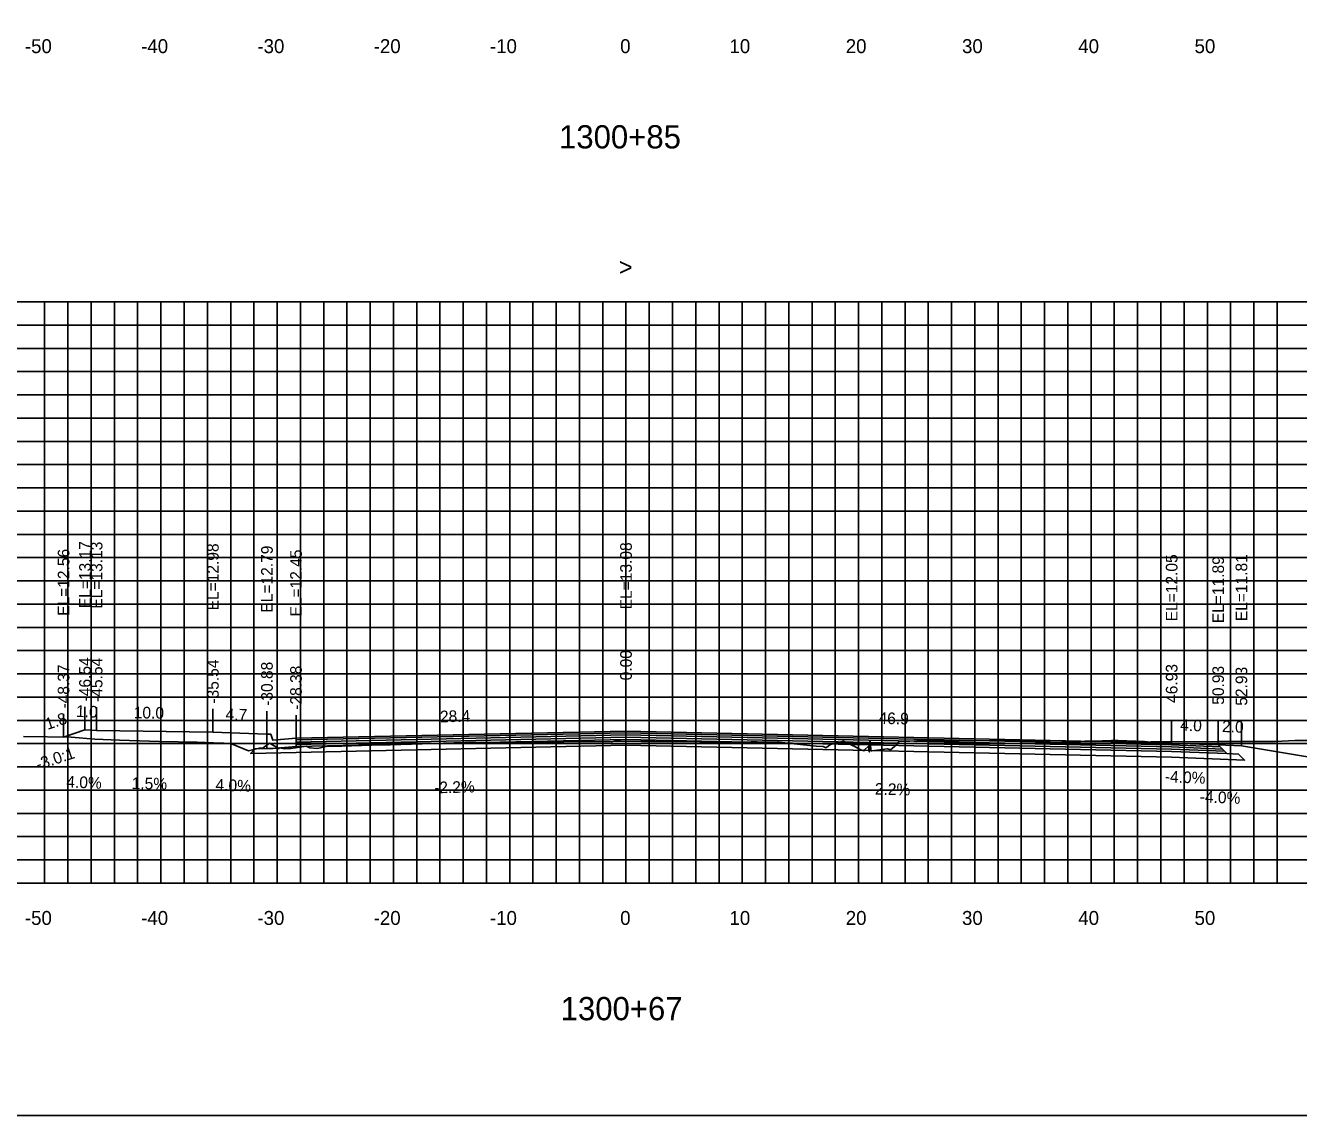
# Model space of a CAD drawing. Extents: x 1797714 to 1804825, y 249015 to 250269.
# Drawn here: x 1802239.4 to 1802348.8, y 250079.4 to 250173.2 of the extents above; entities that cross this region are included whole.
import ezdxf

# ---------------------------------------------------------------- set-up
doc = ezdxf.new("R2010")
doc.units = 0
for name, color, linetype in [('1', 7, 'Continuous'), ('10', 7, 'Continuous'), ('3', 7, 'Continuous'), ('4', 7, 'Continuous'), ('60', 7, 'Continuous'), ('BASE', 7, 'Continuous'), ('CL-CNST', 7, 'Continuous'), ('Level 62', 7, 'Continuous'), ('LOWER BINDER', 7, 'Continuous'), ('M-ROADS', 7, 'Continuous'), ('UPPER BINDER', 7, 'Continuous'), ('WEARING', 7, 'Continuous')]:
    doc.layers.add(name, color=color, linetype=linetype)

msp = doc.modelspace()

# ---------------------------------------------------------------- linework, layer by layer
for p, q in [((1802242.63, 250111.99), (1802242.63, 250113.99)), ((1802244.47, 250112.6), (1802244.47, 250114.6)), ((1802245.47, 250112.56), (1802245.47, 250114.56)), ((1802255.47, 250112.41), (1802255.47, 250114.41)), ((1802260.12, 250112.23), (1802260.12, 250114.23)), ((1802291, 250112.51), (1802291, 250114.51)), ((1802262.62, 250111.89), (1802262.62, 250113.89)), ((1802337.93, 250111.48), (1802337.93, 250113.48)), ((1802341.93, 250111.32), (1802341.93, 250113.32)), ((1802343.93, 250111.24), (1802343.93, 250113.24))]:
    msp.add_line(p, q)
for points in [[(1802141, 250079.43), (1802441, 250079.43), (1802441, 250269.43), (1802141, 250269.43)], [(1802262.62, 250111.89), (1802260.62, 250111.73), (1802260.45, 250112.23), (1802260.12, 250112.23), (1802260.12, 250111.01), (1802260.62, 250111.01), (1802262.62, 250111.17)], [(1802262.62, 250111.89), (1802260.62, 250111.73), (1802260.45, 250112.23), (1802260.12, 250112.23), (1802260.12, 250111.01), (1802260.62, 250111.01), (1802262.62, 250111.17)]]:
    msp.add_lwpolyline(points, close=True)
at = {"layer": '60'}
for p, q in [((1802141, 250099.43), (1802441, 250099.43)), ((1802241, 250099.37), (1802241, 250099.43)), ((1802251, 250099.37), (1802251, 250099.43)), ((1802261, 250099.37), (1802261, 250099.43)), ((1802271, 250099.37), (1802271, 250099.43)), ((1802281, 250099.37), (1802281, 250099.43)), ((1802291, 250099.37), (1802291, 250099.43)), ((1802301, 250099.37), (1802301, 250099.43)), ((1802311, 250099.37), (1802311, 250099.43)), ((1802321, 250099.37), (1802321, 250099.43)), ((1802331, 250099.37), (1802331, 250099.43)), ((1802341, 250099.37), (1802341, 250099.43))]:
    msp.add_line(p, q, dxfattribs=at)
at = {"layer": 'BASE'}
msp.add_lwpolyline([(1802337.93, 250110.26), (1802344.2, 250110.01), (1802343.68, 250110.53), (1802342.68, 250110.57), (1802337.93, 250110.76), (1802291, 250111.79), (1802262.62, 250111.17), (1802260.62, 250111.01), (1802260.12, 250111.01), (1802259.12, 250110.98), (1802258.71, 250110.58), (1802262.62, 250110.67), (1802291, 250111.29)], close=True, dxfattribs=at)
at = {"layer": 'CL-CNST'}
msp.add_lwpolyline([(1802242.63, 250111.99), (1802244.47, 250112.6), (1802245.47, 250112.56), (1802255.47, 250112.41), (1802260.12, 250112.23), (1802260.45, 250112.23), (1802260.62, 250111.73), (1802262.62, 250111.89), (1802291, 250112.51), (1802337.93, 250111.48), (1802341.93, 250111.32), (1802343.93, 250111.24), (1802364.93, 250107.74), (1802368.93, 250107.74), (1802382.11, 250111.03)], dxfattribs=at)
at = {"layer": 'Level 62'}
for p, q in [((1802141, 250149.43), (1802441, 250149.43)), ((1802241, 250099.43), (1802241, 250149.43)), ((1802243, 250099.43), (1802243, 250149.43)), ((1802245, 250099.43), (1802245, 250149.43)), ((1802247, 250099.43), (1802247, 250149.43)), ((1802249, 250099.43), (1802249, 250149.43)), ((1802251, 250099.43), (1802251, 250149.43)), ((1802253, 250099.43), (1802253, 250149.43)), ((1802255, 250099.43), (1802255, 250149.43)), ((1802257, 250099.43), (1802257, 250149.43)), ((1802259, 250099.43), (1802259, 250149.43)), ((1802261, 250099.43), (1802261, 250149.43)), ((1802263, 250099.43), (1802263, 250149.43)), ((1802265, 250099.43), (1802265, 250149.43)), ((1802267, 250099.43), (1802267, 250149.43)), ((1802269, 250099.43), (1802269, 250149.43)), ((1802271, 250099.43), (1802271, 250149.43)), ((1802273, 250099.43), (1802273, 250149.43)), ((1802275, 250099.43), (1802275, 250149.43)), ((1802277, 250099.43), (1802277, 250149.43)), ((1802279, 250099.43), (1802279, 250149.43)), ((1802281, 250099.43), (1802281, 250149.43)), ((1802283, 250099.43), (1802283, 250149.43)), ((1802285, 250099.43), (1802285, 250149.43)), ((1802287, 250099.43), (1802287, 250149.43)), ((1802289, 250099.43), (1802289, 250149.43)), ((1802291, 250099.43), (1802291, 250149.43)), ((1802293, 250099.43), (1802293, 250149.43)), ((1802295, 250099.43), (1802295, 250149.43)), ((1802297, 250099.43), (1802297, 250149.43)), ((1802299, 250099.43), (1802299, 250149.43)), ((1802301, 250099.43), (1802301, 250149.43)), ((1802303, 250099.43), (1802303, 250149.43)), ((1802305, 250099.43), (1802305, 250149.43)), ((1802307, 250099.43), (1802307, 250149.43)), ((1802309, 250099.43), (1802309, 250149.43)), ((1802311, 250099.43), (1802311, 250149.43)), ((1802313, 250099.43), (1802313, 250149.43)), ((1802315, 250099.43), (1802315, 250149.43)), ((1802317, 250099.43), (1802317, 250149.43)), ((1802319, 250099.43), (1802319, 250149.43)), ((1802321, 250099.43), (1802321, 250149.43)), ((1802323, 250099.43), (1802323, 250149.43)), ((1802325, 250099.43), (1802325, 250149.43)), ((1802327, 250099.43), (1802327, 250149.43)), ((1802329, 250099.43), (1802329, 250149.43)), ((1802331, 250099.43), (1802331, 250149.43)), ((1802333, 250099.43), (1802333, 250149.43)), ((1802335, 250099.43), (1802335, 250149.43)), ((1802337, 250099.43), (1802337, 250149.43)), ((1802339, 250099.43), (1802339, 250149.43)), ((1802341, 250099.43), (1802341, 250149.43)), ((1802343, 250099.43), (1802343, 250149.43)), ((1802345, 250099.43), (1802345, 250149.43)), ((1802347, 250099.43), (1802347, 250149.43)), ((1802141, 250147.43), (1802441, 250147.43)), ((1802141, 250145.43), (1802441, 250145.43)), ((1802141, 250143.43), (1802441, 250143.43)), ((1802141, 250141.43), (1802441, 250141.43)), ((1802141, 250139.43), (1802441, 250139.43)), ((1802141, 250137.43), (1802441, 250137.43)), ((1802141, 250135.43), (1802441, 250135.43)), ((1802141, 250133.43), (1802441, 250133.43)), ((1802141, 250131.43), (1802441, 250131.43)), ((1802141, 250129.43), (1802441, 250129.43)), ((1802141, 250127.43), (1802441, 250127.43)), ((1802141, 250125.43), (1802441, 250125.43)), ((1802141, 250123.43), (1802441, 250123.43)), ((1802141, 250121.43), (1802441, 250121.43)), ((1802141, 250119.43), (1802441, 250119.43)), ((1802141, 250117.43), (1802441, 250117.43)), ((1802141, 250115.43), (1802441, 250115.43)), ((1802141, 250113.43), (1802441, 250113.43)), ((1802141, 250111.43), (1802441, 250111.43)), ((1802141, 250109.43), (1802441, 250109.43)), ((1802141, 250107.43), (1802441, 250107.43)), ((1802141, 250105.43), (1802441, 250105.43)), ((1802141, 250103.43), (1802441, 250103.43)), ((1802141, 250101.43), (1802441, 250101.43)), ((1802141, 250099.43), (1802441, 250099.43))]:
    msp.add_line(p, q, dxfattribs=at)
at = {"layer": 'LOWER BINDER'}
for points in [[(1802262.62, 250111.55), (1802291, 250112.17), (1802337.93, 250111.14), (1802342.29, 250110.96), (1802342.48, 250110.77), (1802337.93, 250110.95), (1802291, 250111.98), (1802262.62, 250111.36)], [(1802262.62, 250111.36), (1802291, 250111.98), (1802337.93, 250110.95), (1802342.48, 250110.77), (1802342.68, 250110.57), (1802337.93, 250110.76), (1802291, 250111.79), (1802262.62, 250111.17)]]:
    msp.add_lwpolyline(points, close=True, dxfattribs=at)
at = {"layer": 'M-ROADS'}
msp.add_lwpolyline([(1802239.17, 250112.03), (1802243.28, 250111.98), (1802245.33, 250111.8), (1802247.45, 250111.73), (1802250.88, 250111.6), (1802254.11, 250111.56), (1802255.51, 250111.51), (1802256.23, 250111.46), (1802256.29, 250111.46), (1802256.42, 250111.46), (1802257.06, 250111.41), (1802258.52, 250110.82), (1802259.46, 250111.05), (1802259.8, 250111.07), (1802260.33, 250111.46), (1802261, 250111.09), (1802261.15, 250110.99), (1802261.15, 250111.03), (1802261.18, 250111.07), (1802261.65, 250110.98), (1802262, 250111.02), (1802262.21, 250111.02), (1802263.48, 250111.2), (1802263.82, 250111.07), (1802264.46, 250111.02), (1802265.21, 250111.17), (1802265.49, 250111.22), (1802265.53, 250111.22), (1802265.69, 250111.19), (1802269.11, 250111.29), (1802270.71, 250111.33), (1802277.15, 250111.53), (1802277.31, 250111.53), (1802279.56, 250111.52), (1802279.87, 250111.53), (1802280.06, 250111.53), (1802282.13, 250111.52), (1802283.42, 250111.54), (1802283.53, 250111.54), (1802283.97, 250111.55), (1802287.37, 250111.6), (1802288.04, 250111.6), (1802289.73, 250111.59), (1802290.01, 250111.63), (1802290.09, 250111.64), (1802290.55, 250111.63), (1802292.34, 250111.6), (1802293.51, 250111.62), (1802297.36, 250111.58), (1802299.13, 250111.57), (1802299.77, 250111.55), (1802300.74, 250111.58), (1802301.5, 250111.54), (1802301.78, 250111.57), (1802301.85, 250111.58), (1802302.27, 250111.58), (1802304.11, 250111.56), (1802307.37, 250111.22), (1802307.95, 250111.17), (1802308.18, 250111.08), (1802308.59, 250111.36), (1802309.71, 250111.65), (1802310.54, 250111.24), (1802310.68, 250111.17), (1802310.72, 250111.16), (1802311.13, 250110.92), (1802311.17, 250110.89), (1802311.18, 250110.89), (1802311.18, 250110.89), (1802311.19, 250110.89), (1802311.49, 250110.82), (1802311.52, 250110.88), (1802311.87, 250111.2), (1802311.92, 250110.72), (1802311.93, 250111.35), (1802311.94, 250111.47), (1802312, 250111.64), (1802312.06, 250110.91), (1802312.08, 250110.81), (1802312.08, 250110.8), (1802312.14, 250110.8), (1802313.49, 250110.97), (1802313.76, 250110.88), (1802314.27, 250111.33), (1802314.49, 250111.65), (1802315.42, 250111.65), (1802315.86, 250111.66), (1802315.89, 250111.64), (1802315.91, 250111.65), (1802315.92, 250111.67), (1802315.93, 250111.67), (1802315.95, 250111.61), (1802316.08, 250111.67), (1802316.58, 250111.66), (1802319.08, 250111.66), (1802328.3, 250111.7), (1802328.86, 250111.62), (1802330.45, 250111.64), (1802331.99, 250111.68), (1802332.77, 250111.7), (1802333.34, 250111.7), (1802335.59, 250111.62), (1802336.13, 250111.56), (1802336.14, 250111.57), (1802336.23, 250111.57), (1802336.61, 250111.57), (1802341.89, 250111.62), (1802346.86, 250111.61), (1802348.53, 250111.71), (1802350.02, 250111.71)], dxfattribs=at)
at = {"layer": 'UPPER BINDER'}
msp.add_lwpolyline([(1802262.62, 250111.55), (1802291, 250112.17), (1802337.93, 250111.14), (1802342.29, 250110.96), (1802342.09, 250111.16), (1802337.93, 250111.33), (1802291, 250112.36), (1802262.62, 250111.74)], close=True, dxfattribs=at)
at = {"layer": 'WEARING'}
msp.add_lwpolyline([(1802337.93, 250111.33), (1802342.09, 250111.16), (1802341.93, 250111.32), (1802337.93, 250111.48), (1802291, 250112.51), (1802262.62, 250111.89), (1802262.62, 250111.74), (1802291, 250112.36)], close=True, dxfattribs=at)

# ---------------------------------------------------------------- texts
msp.add_text('-3.0:1', height=1, rotation=18.4349).set_placement((1802240.43, 250109.13))
at = {"layer": '1'}
for s, p in [('1300+85', (1802285.24, 250162.63)), ('1300+67', (1802285.38, 250087.63))]:
    msp.add_text(s, height=2, dxfattribs=at).set_placement(p)
at = {"layer": '10'}
for s, p in [('-50', (1802239.3, 250170.83)), ('-40', (1802249.3, 250170.83)), ('-30', (1802259.3, 250170.83)), ('-20', (1802269.3, 250170.83)), ('-10', (1802279.3, 250170.83)), ('0', (1802290.5, 250170.83)), ('10', (1802299.9, 250170.83)), ('20', (1802309.9, 250170.83)), ('30', (1802319.9, 250170.83)), ('40', (1802329.9, 250170.83)), ('50', (1802339.9, 250170.83)), ('-50', (1802239.3, 250095.83)), ('-40', (1802249.3, 250095.83)), ('-30', (1802259.3, 250095.83)), ('-20', (1802269.3, 250095.83)), ('-10', (1802279.3, 250095.83)), ('0', (1802290.5, 250095.83)), ('10', (1802299.9, 250095.83)), ('20', (1802309.9, 250095.83)), ('30', (1802319.9, 250095.83)), ('40', (1802329.9, 250095.83)), ('50', (1802339.9, 250095.83))]:
    msp.add_text(s, height=1.2, dxfattribs=at).set_placement(p)
at = {"layer": '3'}
for s, p in [('EL=13.17', (1802244.97, 250123.08)), ('EL=13.13', (1802245.97, 250123.04)), ('EL=12.98', (1802255.97, 250122.89)), ('EL=12.79', (1802260.62, 250122.7)), ('EL=13.08', (1802291.5, 250122.98)), ('EL=12.56', (1802243.13, 250122.42)), ('EL=12.45', (1802263.12, 250122.36)), ('EL=12.05', (1802338.43, 250121.95)), ('EL=11.89', (1802342.43, 250121.79)), ('EL=11.81', (1802344.43, 250121.96)), ('0.00', (1802291.5, 250116.87)), ('-46.54', (1802244.97, 250115.06)), ('-45.54', (1802245.97, 250115.02)), ('-35.54', (1802255.97, 250114.87)), ('-30.88', (1802260.62, 250114.68)), ('-48.37', (1802243.13, 250114.45)), ('-28.38', (1802263.12, 250114.34)), ('46.93', (1802338.43, 250114.93)), ('50.93', (1802342.43, 250114.77)), ('52.93', (1802344.43, 250114.69))]:
    msp.add_text(s, height=1, rotation=90, dxfattribs=at).set_placement(p)
at = {"layer": '4'}
for s, rotation, p in [('1.8', 18.4349, (1802241.25, 250112.6)), ('1.0', 357.7094, (1802243.69, 250113.73)), ('10.0', 359.1406, (1802248.66, 250113.61)), ('4.7', 357.7094, (1802256.55, 250113.47)), ('28.4', 1.2603, (1802275.01, 250113.26)), ('46.9', 358.7397, (1802312.71, 250113.13)), ('4.0', 357.7094, (1802338.65, 250112.55)), ('2.0', 357.7094, (1802342.25, 250112.43)), ('4.0%', 357.7094, (1802242.85, 250107.66)), ('1.5%', 359.1406, (1802248.48, 250107.52)), ('-4.0%', 357.7094, (1802337.33, 250108.11)), ('4.0%', 357.7094, (1802255.68, 250107.4)), ('-2.2%', 1.2603, (1802274.51, 250107.15)), ('-2.2%', 358.7397, (1802311.95, 250107.05)), ('-4.0%', 357.7094, (1802340.33, 250106.38))]:
    msp.add_text(s, height=1, rotation=rotation, dxfattribs=at).set_placement(p)
at = {"layer": '60'}
msp.add_text('>', height=1.5, dxfattribs=at).set_placement((1802290.39, 250151.68))

doc.saveas('drawing.dxf')
